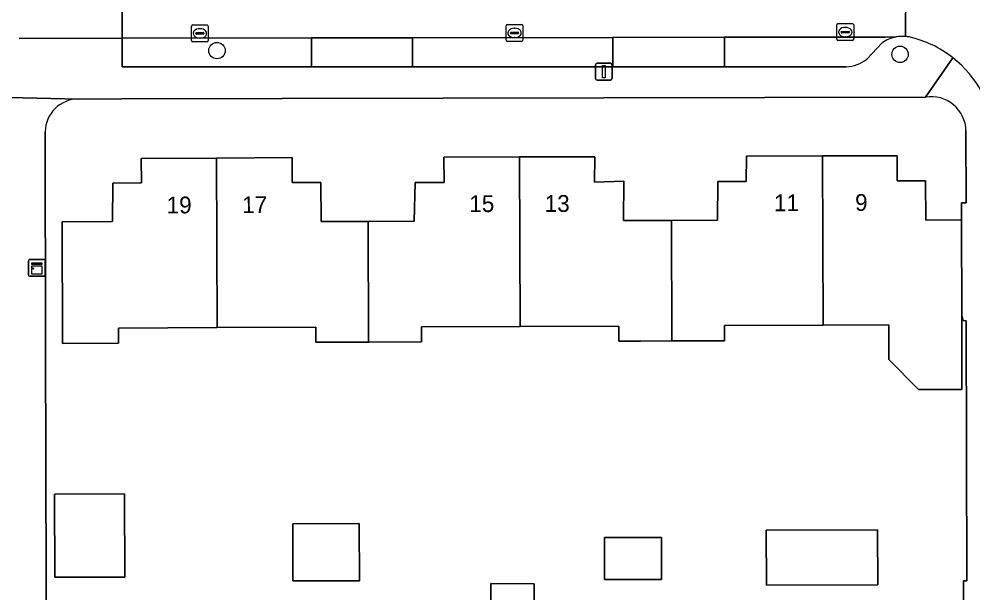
# Model space of a CAD drawing. Extents: x 160455 to 162082, y 388339 to 389736.
# Drawn here: x 160888.5 to 160945.3, y 388589.6 to 388623.8 of the extents above; entities that cross this region are included whole.
import ezdxf

# ---------------------------------------------------------------- set-up
doc = ezdxf.new("R2010")
doc.units = 0
for name, color, linetype in [('IMGEO_Boom', 7, 'Continuous'), ('IMGEO_Erf', 7, 'Continuous'), ('IMGEO_Kast', 7, 'Continuous'), ('IMGEO_Kolk', 7, 'Continuous'), ('IMGEO_Lichtmast', 7, 'Continuous'), ('IMGEO_Muur', 7, 'Continuous'), ('IMGEO_Pand', 7, 'Continuous'), ('IMGEO_Pand_nummerreeks', 7, 'Continuous'), ('IMGEO_Parkeervlak_open', 7, 'Continuous'), ('IMGEO_Rijbaan_lokaal_open', 7, 'Continuous'), ('IMGEO_Voetpad_open', 7, 'Continuous')]:
    doc.layers.add(name, color=color, linetype=linetype)

msp = doc.modelspace()

# ---------------------------------------------------------------- linework, layer by layer
at = {"layer": 'IMGEO_Boom'}
for centre in [(160900.313, 388621.931), (160940.984, 388621.708)]:
    msp.add_circle(centre, 0.489, dxfattribs=at)
at = {"layer": 'IMGEO_Erf'}
for points in [[(160942.507, 388619.163), (160894.635, 388619.052), (160892.082, 388619.048)], [(160890.091, 388617.099), (160890.112, 388604.489), (160890.136, 388590.2), (160890.205, 388547.5)], [(160940.315, 388603.537), (160940.308, 388605.589), (160936.402, 388605.573), (160930.532, 388605.55), (160930.535, 388604.65), (160927.396, 388604.637), (160925.536, 388604.63), (160924.245, 388604.625), (160924.241, 388605.524), (160918.368, 388605.501), (160912.49, 388605.478), (160912.493, 388604.578), (160909.341, 388604.565), (160906.203, 388604.553), (160906.199, 388605.452), (160900.328, 388605.429), (160894.449, 388605.406), (160894.452, 388604.506), (160891.122, 388604.493), (160891.102, 388611.722), (160894.103, 388611.743), (160894.112, 388614.038), (160895.811, 388614.047), (160895.792, 388615.504), (160900.288, 388615.533), (160904.787, 388615.563), (160904.794, 388614.07), (160906.503, 388614.075), (160906.514, 388611.751), (160909.313, 388611.758), (160912.064, 388611.765), (160912.112, 388614.081), (160913.831, 388614.077), (160913.82, 388615.592), (160918.328, 388615.6), (160922.803, 388615.608), (160922.8, 388614.095), (160924.54, 388614.161), (160924.513, 388611.803), (160927.367, 388611.82), (160930.12, 388611.837), (160930.127, 388614.132), (160931.83, 388614.136), (160931.842, 388615.637), (160936.362, 388615.655), (160940.812, 388615.672), (160940.818, 388614.173), (160942.508, 388614.18), (160942.516, 388611.839), (160944.635, 388611.85), (160944.632, 388612.867), (160944.915, 388612.872), (160944.907, 388617.16)], [(160944.828, 388555.395), (160944.768, 388590.348), (160944.952, 388590.348), (160944.927, 388605.843), (160944.746, 388605.849), (160944.655, 388606.156), (160944.671, 388601.751), (160942.072, 388601.742), (160940.315, 388603.537)]]:
    msp.add_lwpolyline(points, dxfattribs=at)
for points in [[(160894.826, 388590.57), (160890.654, 388590.56), (160890.642, 388595.51), (160894.814, 388595.519)], [(160908.797, 388590.354), (160904.833, 388590.34), (160904.821, 388593.742), (160908.785, 388593.756)], [(160933.017, 388593.368), (160939.645, 388593.381), (160939.652, 388590.109), (160933.023, 388590.096)], [(160926.775, 388592.935), (160926.78, 388590.421), (160923.389, 388590.414), (160923.384, 388592.928)], [(160919.16, 388583.485), (160919.141, 388580.449), (160916.556, 388580.465), (160916.575, 388583.48), (160916.616, 388590.185), (160919.201, 388590.17)]]:
    msp.add_lwpolyline(points, close=True, dxfattribs=at)
for centre, radius, start, end in [((160942.833, 388617.114), 2.075, 1.271, 99.0334), ((160892.056, 388617.083), 1.965, 89.2408, 179.5377)]:
    msp.add_arc(centre, radius, start, end, dxfattribs=at)
at = {"layer": 'IMGEO_Kast'}
for p, q in [((160889.167, 388609.49), (160890.008, 388609.49)), ((160890.008, 388609.49), (160889.167, 388609.49)), ((160890.092, 388609.415), (160890.092, 388608.574)), ((160890.092, 388608.574), (160890.092, 388609.415)), ((160889.092, 388608.565), (160889.092, 388609.406)), ((160889.092, 388609.406), (160889.092, 388608.565)), ((160890.017, 388608.49), (160889.176, 388608.49)), ((160889.176, 388608.49), (160890.017, 388608.49))]:
    msp.add_line(p, q, dxfattribs=at)
for points in [[(160889.287, 388609.28), (160889.887, 388609.28), (160889.887, 388609.195), (160889.287, 388609.195), (160889.287, 388609.28)], [(160889.287, 388609.105), (160889.887, 388609.105), (160889.887, 388608.616), (160889.287, 388608.616), (160889.287, 388609.105)]]:
    msp.add_lwpolyline(points, dxfattribs=at)
msp.add_circle((160889.371, 388608.954), 0.0377, dxfattribs=at)
for centre, start, end in [((160889.17, 388609.412), 92.4484, 184.2845), ((160889.17, 388609.412), 92.4484, 184.2845), ((160890.014, 388609.412), 2.4484, 94.2845), ((160890.014, 388609.412), 2.4484, 94.2845), ((160889.17, 388608.568), 182.4484, 274.2845), ((160889.17, 388608.568), 182.4484, 274.2845), ((160890.014, 388608.568), 272.4484, 4.2845), ((160890.014, 388608.568), 272.4484, 4.2845)]:
    msp.add_arc(centre, 0.0779, start, end, dxfattribs=at)
at = {"layer": 'IMGEO_Kolk'}
for p, q in [((160898.797, 388622.533), (160898.797, 388623.385)), ((160898.872, 388623.459), (160899.724, 388623.459)), ((160899.285, 388623.239), (160899.31, 388623.239)), ((160899.798, 388623.385), (160899.798, 388622.533)), ((160917.528, 388622.558), (160917.528, 388623.41)), ((160917.603, 388623.484), (160918.455, 388623.484)), ((160918.016, 388623.264), (160918.041, 388623.264)), ((160918.529, 388623.41), (160918.529, 388622.558)), ((160937.222, 388622.611), (160937.222, 388623.463)), ((160937.297, 388623.537), (160938.149, 388623.537)), ((160937.481, 388623.031), (160937.481, 388623.043)), ((160937.524, 388623.08), (160937.922, 388623.08)), ((160937.71, 388623.317), (160937.735, 388623.317)), ((160937.965, 388623.043), (160937.965, 388623.031)), ((160938.223, 388623.463), (160938.223, 388622.611)), ((160899.056, 388622.953), (160899.056, 388622.965)), ((160899.494, 388622.916), (160899.096, 388622.916)), ((160899.099, 388623.002), (160899.497, 388623.002)), ((160899.308, 388622.679), (160899.283, 388622.679)), ((160899.54, 388622.965), (160899.54, 388622.953)), ((160918.455, 388622.484), (160917.603, 388622.484)), ((160917.787, 388622.978), (160917.787, 388622.99)), ((160918.225, 388622.941), (160917.827, 388622.941)), ((160917.83, 388623.027), (160918.228, 388623.027)), ((160918.039, 388622.704), (160918.014, 388622.704)), ((160918.271, 388622.99), (160918.271, 388622.978)), ((160938.149, 388622.537), (160937.297, 388622.537)), ((160937.919, 388622.994), (160937.521, 388622.994)), ((160937.733, 388622.757), (160937.708, 388622.757)), ((160899.724, 388622.459), (160898.872, 388622.459))]:
    msp.add_line(p, q, dxfattribs=at)
for points in [[(160898.797, 388622.533), (160898.797, 388623.385)], [(160898.872, 388623.459), (160899.724, 388623.459)], [(160899.798, 388623.385), (160899.798, 388622.533)], [(160917.528, 388622.558), (160917.528, 388623.41)], [(160917.603, 388623.484), (160918.455, 388623.484)], [(160918.529, 388623.41), (160918.529, 388622.558)], [(160937.222, 388622.611), (160937.222, 388623.463)], [(160937.297, 388623.537), (160938.149, 388623.537)], [(160938.223, 388623.463), (160938.223, 388622.611)], [(160918.455, 388622.484), (160917.603, 388622.484)], [(160938.149, 388622.537), (160937.297, 388622.537)], [(160899.724, 388622.459), (160898.872, 388622.459)]]:
    msp.add_lwpolyline(points, dxfattribs=at)
for centre, radius, start, end in [((160898.874, 388623.383), 0.0765, 91.552, 178.448), ((160898.874, 388623.383), 0.0765, 91.552, 178.448), ((160899.722, 388623.383), 0.0765, 1.552, 88.448), ((160899.722, 388623.383), 0.0765, 1.552, 88.448), ((160917.605, 388623.408), 0.0765, 91.552, 178.448), ((160917.605, 388623.408), 0.0765, 91.552, 178.448), ((160918.453, 388623.408), 0.0765, 1.552, 88.448), ((160918.453, 388623.408), 0.0765, 1.552, 88.448), ((160937.299, 388623.461), 0.0765, 91.552, 178.448), ((160937.299, 388623.461), 0.0765, 91.552, 178.448), ((160937.521, 388623.04), 0.0403, 85.8775, 175.7526), ((160937.926, 388623.042), 0.0386, 1.7309, 96.639), ((160938.147, 388623.461), 0.0765, 1.552, 88.448), ((160938.147, 388623.461), 0.0765, 1.552, 88.448), ((160898.874, 388622.535), 0.0765, 181.552, 268.448), ((160898.874, 388622.535), 0.0765, 181.552, 268.448), ((160899.096, 388622.962), 0.0403, 85.8775, 175.7526), ((160899.093, 388622.952), 0.0366, 178.938, 274.7102), ((160899.497, 388622.959), 0.043, 264.8664, 352.4533), ((160899.501, 388622.964), 0.0386, 1.7309, 96.639), ((160899.722, 388622.535), 0.0765, 271.552, 358.448), ((160899.722, 388622.535), 0.0765, 271.552, 358.448), ((160917.605, 388622.56), 0.0765, 181.552, 268.448), ((160917.605, 388622.56), 0.0765, 181.552, 268.448), ((160917.827, 388622.987), 0.0403, 85.8775, 175.7526), ((160917.824, 388622.977), 0.0366, 178.938, 274.7102), ((160918.228, 388622.984), 0.043, 264.8664, 352.4533), ((160918.232, 388622.989), 0.0386, 1.7309, 96.639), ((160918.453, 388622.56), 0.0765, 271.552, 358.448), ((160918.453, 388622.56), 0.0765, 271.552, 358.448), ((160937.299, 388622.613), 0.0765, 181.552, 268.448), ((160937.299, 388622.613), 0.0765, 181.552, 268.448), ((160937.518, 388623.03), 0.0366, 178.938, 274.7102), ((160937.922, 388623.037), 0.043, 264.8664, 352.4533), ((160938.147, 388622.613), 0.0765, 271.552, 358.448), ((160938.147, 388622.613), 0.0765, 271.552, 358.448)]:
    msp.add_arc(centre, radius, start, end, dxfattribs=at)
for centre, major_axis, ratio, start_param, end_param in [((160899.284, 388622.959), (-0.387, 0.002), 0.722429, 4.712389, 7.853982), ((160899.309, 388622.959), (-0.39, 0.002), 0.717154, 1.570796, 4.712389), ((160918.015, 388622.984), (-0.387, 0.002), 0.722429, 4.712389, 7.853982), ((160918.04, 388622.984), (-0.39, 0.002), 0.717154, 1.570796, 4.712389), ((160937.709, 388623.037), (-0.387, 0.002), 0.722429, 4.712389, 7.853982), ((160937.734, 388623.037), (-0.39, 0.002), 0.717154, 1.570796, 4.712389)]:
    msp.add_ellipse(centre, major_axis=major_axis, ratio=ratio, start_param=start_param, end_param=end_param, dxfattribs=at)
at = {"layer": 'IMGEO_Lichtmast'}
for p, q in [((160922.847, 388620.279), (160922.847, 388621.079)), ((160922.847, 388621.079), (160922.847, 388620.279)), ((160922.947, 388621.179), (160923.737, 388621.179)), ((160923.737, 388621.179), (160922.947, 388621.179)), ((160923.837, 388621.079), (160923.837, 388620.279)), ((160923.837, 388620.279), (160923.837, 388621.079)), ((160923.737, 388620.179), (160922.947, 388620.179)), ((160922.947, 388620.179), (160923.737, 388620.179))]:
    msp.add_line(p, q, dxfattribs=at)
msp.add_lwpolyline([(160923.267, 388621.054), (160923.417, 388621.054), (160923.417, 388620.304), (160923.267, 388620.304), (160923.267, 388621.054)], dxfattribs=at)
for centre, start, end in [((160922.947, 388621.079), 90, 180), ((160922.947, 388621.079), 90, 180), ((160923.737, 388621.079), 0, 90), ((160923.737, 388621.079), 360, 90), ((160922.947, 388620.279), 180, 270), ((160922.947, 388620.279), 180, 270), ((160923.737, 388620.279), 270, 0), ((160923.737, 388620.279), 270, 0)]:
    msp.add_arc(centre, 0.1, start, end, dxfattribs=at)
at = {"layer": 'IMGEO_Muur'}
msp.add_lwpolyline([(160890.112, 388604.489), (160890.136, 388590.2)], dxfattribs=at)
at = {"layer": 'IMGEO_Pand'}
for points in [[(160936.402, 388605.573), (160940.308, 388605.589), (160940.315, 388603.537), (160942.072, 388601.742), (160944.671, 388601.751), (160944.655, 388606.156), (160944.635, 388611.85), (160942.516, 388611.839), (160942.508, 388614.18), (160940.818, 388614.173), (160940.812, 388615.672), (160936.362, 388615.655)], [(160900.288, 388615.533), (160895.792, 388615.504), (160895.811, 388614.047), (160894.112, 388614.038), (160894.103, 388611.743), (160891.102, 388611.722), (160891.122, 388604.493), (160894.452, 388604.506), (160894.449, 388605.406), (160900.328, 388605.429)], [(160909.341, 388604.565), (160909.313, 388611.758), (160906.514, 388611.751), (160906.503, 388614.075), (160904.794, 388614.07), (160904.787, 388615.563), (160900.288, 388615.533), (160900.328, 388605.429), (160906.199, 388605.452), (160906.203, 388604.553)], [(160909.341, 388604.565), (160912.493, 388604.578), (160912.49, 388605.478), (160918.368, 388605.501), (160918.328, 388615.6), (160913.82, 388615.592), (160913.831, 388614.077), (160912.112, 388614.081), (160912.064, 388611.765), (160909.313, 388611.758)], [(160918.328, 388615.6), (160918.368, 388605.501), (160924.241, 388605.524), (160924.245, 388604.625), (160925.536, 388604.63), (160927.396, 388604.637), (160927.367, 388611.82), (160924.513, 388611.803), (160924.54, 388614.161), (160922.8, 388614.095), (160922.803, 388615.608)], [(160936.402, 388605.573), (160936.362, 388615.655), (160931.842, 388615.637), (160931.83, 388614.136), (160930.127, 388614.132), (160930.12, 388611.837), (160927.367, 388611.82), (160927.396, 388604.637), (160930.535, 388604.65), (160930.532, 388605.55)], [(160894.826, 388590.57), (160894.814, 388595.519), (160890.642, 388595.51), (160890.654, 388590.56)], [(160908.797, 388590.354), (160908.785, 388593.756), (160904.821, 388593.742), (160904.833, 388590.34)], [(160933.017, 388593.368), (160933.023, 388590.096), (160939.652, 388590.109), (160939.645, 388593.381)], [(160926.78, 388590.421), (160926.775, 388592.935), (160923.384, 388592.928), (160923.389, 388590.414)], [(160916.575, 388583.48), (160919.16, 388583.485), (160919.201, 388590.17), (160916.616, 388590.185)]]:
    msp.add_lwpolyline(points, close=True, dxfattribs=at)
at = {"layer": 'IMGEO_Parkeervlak_open'}
for points in [[(160905.936, 388622.685), (160894.662, 388622.666), (160894.665, 388621.166), (160894.665, 388620.969), (160905.685, 388620.969), (160905.94, 388620.969), (160905.939, 388621.191)], [(160911.947, 388622.695), (160905.936, 388622.685), (160905.939, 388621.191), (160905.94, 388620.969), (160911.951, 388620.969), (160911.95, 388621.194)], [(160923.885, 388622.715), (160911.947, 388622.695), (160911.95, 388621.194), (160911.951, 388620.969), (160912.33, 388620.969), (160923.701, 388620.969), (160923.889, 388620.969), (160923.889, 388621.227)], [(160930.524, 388622.726), (160923.885, 388622.715), (160923.889, 388621.227), (160923.889, 388620.969), (160930.529, 388620.969)]]:
    msp.add_lwpolyline(points, close=True, dxfattribs=at)
for points in [[(160940.749, 388622.743), (160940.085, 388622.742), (160930.524, 388622.726), (160930.529, 388620.969), (160937.784, 388620.974)], [(160938.997, 388621.431), (160939.928, 388622.39)]]:
    msp.add_lwpolyline(points, dxfattribs=at)
for centre, radius, start, end in [((160941.141, 388620.701), 2.079, 100.8553, 125.6766), ((160937.763, 388622.867), 1.893, 270.6252, 310.6628)]:
    msp.add_arc(centre, radius, start, end, dxfattribs=at)
at = {"layer": 'IMGEO_Rijbaan_lokaal_open'}
for points in [[(160957.122, 388623.1), (160957.285, 388623.088), (160957.279, 388627.635), (160956.983, 388627.6), (160941.339, 388627.57), (160941.315, 388623.065), (160941.313, 388622.774)], [(160888.531, 388622.655), (160894.662, 388622.666), (160894.661, 388627.437)], [(160941.339, 388627.57), (160934.176, 388627.549), (160927.88, 388627.531), (160916.213, 388627.498), (160909.903, 388627.48), (160898.208, 388627.447), (160894.661, 388627.437), (160894.662, 388622.666), (160905.936, 388622.685), (160911.947, 388622.695), (160923.885, 388622.715), (160930.524, 388622.726), (160940.085, 388622.742), (160940.749, 388622.743)], [(160941.313, 388622.774), (160941.315, 388623.065), (160941.339, 388627.57)]]:
    msp.add_lwpolyline(points, dxfattribs=at)
for centre, radius, start, end in [((160941.143, 388620.729), 2.052, 85.2364, 101.0558), ((160941.08, 388620.25), 2.535, 79.5878, 84.7228), ((160940.091, 388616.378), 6.527, 51.789, 77.1882), ((160940.092, 388616.381), 6.524, 4.885, 51.7793)]:
    msp.add_arc(centre, radius, start, end, dxfattribs=at)
at = {"layer": 'IMGEO_Voetpad_open'}
for points in [[(160887.053, 388622.546), (160887.065, 388619.167), (160892.082, 388619.048), (160894.635, 388619.052), (160942.507, 388619.163), (160944.128, 388621.507)], [(160894.665, 388620.969), (160894.665, 388621.166), (160894.662, 388622.666), (160888.531, 388622.655)], [(160939.928, 388622.39), (160938.997, 388621.431)], [(160944.128, 388621.507), (160942.507, 388619.163)], [(160937.784, 388620.974), (160930.529, 388620.969), (160923.889, 388620.969), (160923.701, 388620.969), (160912.33, 388620.969), (160911.951, 388620.969), (160905.94, 388620.969), (160905.685, 388620.969), (160894.665, 388620.969)], [(160892.082, 388619.048), (160887.065, 388619.167), (160887.078, 388615.554), (160887.189, 388547.484), (160890.205, 388547.5), (160890.136, 388590.2)], [(160890.136, 388590.2), (160890.112, 388604.489), (160890.091, 388617.099)], [(160944.907, 388617.16), (160944.915, 388612.872), (160944.632, 388612.867), (160944.635, 388611.85), (160944.655, 388606.156), (160944.746, 388605.849), (160944.927, 388605.843), (160944.952, 388590.348), (160944.768, 388590.348), (160944.828, 388555.395), (160944.685, 388554.654), (160944.681, 388550.218)]]:
    msp.add_lwpolyline(points, dxfattribs=at)
for centre, radius, start, end in [((160941.141, 388620.701), 2.079, 100.8553, 125.6766), ((160941.143, 388620.729), 2.052, 85.2364, 101.0558), ((160941.08, 388620.25), 2.535, 79.5878, 84.7228), ((160940.091, 388616.378), 6.527, 51.789, 77.1882), ((160937.763, 388622.867), 1.893, 270.6252, 310.6628), ((160940.092, 388616.381), 6.524, 4.885, 51.7793), ((160942.833, 388617.114), 2.075, 1.271, 99.0334), ((160892.056, 388617.083), 1.965, 89.2408, 179.5377)]:
    msp.add_arc(centre, radius, start, end, dxfattribs=at)

# ---------------------------------------------------------------- texts
at = {"layer": 'IMGEO_Pand_nummerreeks'}
for s, rotation, p in [('9', 0.2236, (160938.308, 388612.382)), ('19', 0.2357, (160897.32, 388612.23)), ('17', 0.2357, (160901.817, 388612.249)), ('15', 0.1021, (160915.337, 388612.314)), ('13', 0.1021, (160919.828, 388612.322)), ('11', 0.2236, (160933.477, 388612.364))]:
    msp.add_text(s, height=1, rotation=rotation, dxfattribs=at).set_placement(p)

doc.saveas('drawing.dxf')
